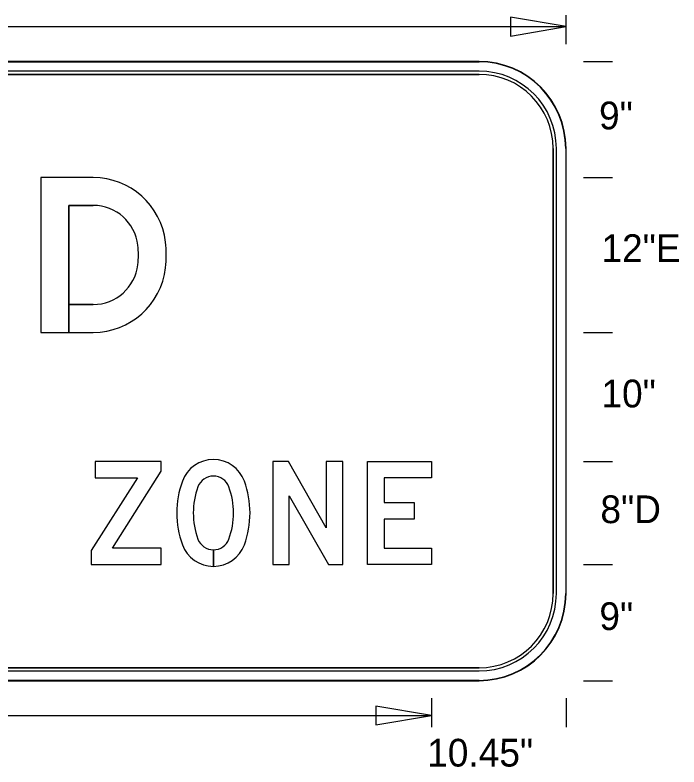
# Model space of a CAD drawing. Extents: x 0 to 770, y 0 to 495.
# Drawn here: x 679.6 to 763.5, y 379.4 to 474.2 of the extents above; entities that cross this region are included whole.
import ezdxf

# ---------------------------------------------------------------- set-up
doc = ezdxf.new("R2010")
doc.units = 0
for name, color, linetype in [('Dimension', 7, 'Continuous'), ('GSBWFill', 7, 'Continuous'), ('GSColorFill', 7, 'Continuous'), ('GSDims', 7, 'Continuous'), ('GSOutline', 7, 'Continuous'), ('TextStructures', 7, 'Continuous')]:
    doc.layers.add(name, color=color, linetype=linetype)

msp = doc.modelspace()

# ---------------------------------------------------------------- linework, layer by layer
at = {"layer": 'Dimension'}
for points in [[(749.208, 472.74), (742.192, 473.929), (742.192, 471.551)], [(732.22, 385.844), (725.203, 387.032), (725.203, 384.655)]]:
    msp.add_lwpolyline(points, close=True, dxfattribs=at)
at = {"layer": 'GSBWFill'}
for p, q in [((738.224, 468.346), (603.974, 468.346)), ((738.224, 467.126), (603.974, 467.126)), ((603.974, 466.719), (738.224, 466.719)), ((747.581, 457.362), (747.581, 401.221)), ((747.988, 401.221), (747.988, 457.362)), ((749.208, 401.221), (749.208, 457.362)), ((686.429, 434.174), (689.519, 434.174)), ((704.686, 406.738), (704.686, 404.655)), ((704.687, 404.655), (704.687, 406.738)), ((738.224, 391.864), (603.978, 391.864)), ((603.978, 391.458), (738.224, 391.458)), ((603.974, 390.237), (738.224, 390.237))]:
    msp.add_line(p, q, dxfattribs=at)
for points in [[(689.519, 453.701), (682.913, 453.701), (682.913, 434.174), (686.428, 434.174), (686.428, 450.186), (689.519, 450.186)], [(689.519, 437.688), (686.429, 437.688), (686.429, 434.174)]]:
    msp.add_lwpolyline(points, dxfattribs=at)
for points in [[(695.104, 415.818), (689.259, 406.64), (689.259, 404.883), (698.112, 404.883), (698.112, 406.966), (691.936, 406.966), (698.112, 416.664), (698.112, 417.901), (689.78, 417.901), (689.78, 415.818)], [(721.024, 404.883), (721.024, 417.901), (718.941, 417.901), (718.941, 409.537), (714.161, 417.901), (712.172, 417.901), (712.172, 404.883), (714.254, 404.883), (714.254, 413.54), (719.201, 404.883)], [(732.22, 415.818), (726.231, 415.818), (726.231, 412.694), (730.017, 412.694), (730.017, 410.611), (726.231, 410.611), (726.231, 406.966), (732.22, 406.966), (732.22, 404.883), (724.148, 404.883), (724.148, 417.901), (732.22, 417.901)]]:
    msp.add_lwpolyline(points, close=True, dxfattribs=at)
for centre, radius, start, end in [((738.224, 457.362), 10.984, 0, 90), ((738.224, 457.362), 9.764, 0, 90), ((738.224, 457.362), 9.357, 0, 90), ((689.519, 444.523), 9.178, 6.50025, 90), ((689.519, 444.523), 5.663, 6.50025, 90), ((684.378, 443.937), 10.838, 353.49975, 6.50025), ((684.378, 443.937), 14.353, 353.49975, 6.50025), ((689.519, 443.351), 5.663, 270, 353.49975), ((689.519, 443.351), 9.178, 270, 353.49975), ((704.686, 413.963), 4.166, 20.0987, 159.9013), ((704.686, 413.963), 2.083, 20.0987, 159.9013), ((711.712, 411.392), 11.648, 159.9013, 200.0987), ((711.712, 411.392), 9.565, 159.9013, 200.0987), ((697.66, 411.392), 9.565, 339.9013, 20.0987), ((697.66, 411.392), 11.648, 339.9013, 20.0987), ((704.686, 408.821), 2.083, 200.0987, 270), ((704.686, 408.821), 2.083, 270.01791, 339.9013), ((704.686, 408.821), 4.166, 200.0987, 270), ((704.686, 408.821), 4.166, 270.00895, 339.9013), ((738.224, 401.221), 9.764, 270, 0), ((738.224, 401.221), 9.357, 270, 0), ((738.224, 401.221), 10.984, 270, 0)]:
    msp.add_arc(centre, radius, start, end, dxfattribs=at)
at = {"layer": 'GSColorFill'}
for p, q in [((738.224, 468.346), (603.974, 468.346)), ((738.224, 468.346), (603.974, 468.346)), ((603.974, 468.306), (738.224, 468.306)), ((738.224, 467.126), (603.974, 467.126)), ((603.974, 466.719), (738.224, 466.719)), ((747.581, 457.362), (747.581, 401.221)), ((747.988, 401.221), (747.988, 457.362)), ((749.168, 457.362), (749.168, 401.221)), ((749.208, 401.221), (749.208, 457.362)), ((749.208, 401.221), (749.208, 457.362)), ((686.429, 434.174), (689.519, 434.174)), ((704.686, 406.738), (704.686, 404.655)), ((704.687, 404.655), (704.687, 406.738)), ((738.224, 391.864), (603.978, 391.864)), ((603.978, 391.458), (738.224, 391.458)), ((603.974, 390.237), (738.224, 390.237)), ((738.224, 390.278), (603.975, 390.278)), ((603.975, 390.237), (738.224, 390.237))]:
    msp.add_line(p, q, dxfattribs=at)
for points in [[(689.519, 453.701), (682.913, 453.701), (682.913, 434.174), (686.428, 434.174), (686.428, 450.186), (689.519, 450.186)], [(689.519, 437.688), (686.429, 437.688), (686.429, 434.174)]]:
    msp.add_lwpolyline(points, dxfattribs=at)
for points in [[(695.104, 415.818), (689.259, 406.64), (689.259, 404.883), (698.112, 404.883), (698.112, 406.966), (691.936, 406.966), (698.112, 416.664), (698.112, 417.901), (689.78, 417.901), (689.78, 415.818)], [(721.024, 404.883), (721.024, 417.901), (718.941, 417.901), (718.941, 409.537), (714.161, 417.901), (712.172, 417.901), (712.172, 404.883), (714.254, 404.883), (714.254, 413.54), (719.201, 404.883)], [(732.22, 415.818), (726.231, 415.818), (726.231, 412.694), (730.017, 412.694), (730.017, 410.611), (726.231, 410.611), (726.231, 406.966), (732.22, 406.966), (732.22, 404.883), (724.148, 404.883), (724.148, 417.901), (732.22, 417.901)]]:
    msp.add_lwpolyline(points, close=True, dxfattribs=at)
for centre, radius, start, end in [((738.224, 457.362), 10.984, 0, 90), ((738.224, 457.362), 10.984, 0, 90), ((738.224, 457.362), 10.943, 0, 90), ((738.224, 457.362), 9.764, 0, 90), ((738.224, 457.362), 9.357, 0, 90), ((689.519, 444.523), 9.178, 6.50025, 90), ((689.519, 444.523), 5.663, 6.50025, 90), ((684.378, 443.937), 10.838, 353.49975, 6.50025), ((684.378, 443.937), 14.353, 353.49975, 6.50025), ((689.519, 443.351), 5.663, 270, 353.49975), ((689.519, 443.351), 9.178, 270, 353.49975), ((704.686, 413.963), 4.166, 20.0987, 159.9013), ((704.686, 413.963), 2.083, 20.0987, 159.9013), ((711.712, 411.392), 11.648, 159.9013, 200.0987), ((711.712, 411.392), 9.565, 159.9013, 200.0987), ((697.66, 411.392), 9.565, 339.9013, 20.0987), ((697.66, 411.392), 11.648, 339.9013, 20.0987), ((704.686, 408.821), 2.083, 200.0987, 270), ((704.686, 408.821), 2.083, 270.01791, 339.9013), ((704.686, 408.821), 4.166, 200.0987, 270), ((704.686, 408.821), 4.166, 270.00895, 339.9013), ((738.224, 401.221), 10.984, 270, 0), ((738.224, 401.221), 9.764, 270, 0), ((738.224, 401.221), 9.357, 270, 0), ((738.224, 401.221), 10.984, 270, 0), ((738.224, 401.221), 10.943, 270, 0)]:
    msp.add_arc(centre, radius, start, end, dxfattribs=at)
at = {"layer": 'GSDims'}
for p, q in [((749.208, 470.543), (749.208, 474.205)), ((592.99, 472.74), (749.208, 472.74)), ((751.405, 468.346), (755.066, 468.346)), ((751.405, 453.701), (755.066, 453.701)), ((751.405, 453.701), (755.066, 453.701)), ((751.405, 434.174), (755.066, 434.174)), ((751.405, 434.174), (755.066, 434.174)), ((751.405, 417.901), (755.066, 417.901)), ((751.405, 417.901), (755.066, 417.901)), ((751.405, 404.883), (755.066, 404.883)), ((751.405, 404.883), (755.066, 404.883)), ((751.405, 390.237), (755.066, 390.237)), ((732.22, 388.04), (732.22, 384.379)), ((732.22, 388.04), (732.22, 384.379)), ((749.208, 388.04), (749.208, 384.379)), ((609.979, 385.844), (732.22, 385.844))]:
    msp.add_line(p, q, dxfattribs=at)
at = {"layer": 'GSOutline'}
for p, q in [((738.224, 468.346), (603.974, 468.346)), ((738.224, 467.126), (603.974, 467.126)), ((738.224, 466.719), (603.974, 466.719)), ((747.581, 401.221), (747.581, 457.362)), ((747.988, 401.221), (747.988, 457.362)), ((749.208, 401.221), (749.208, 457.362)), ((686.428, 437.688), (689.519, 437.688)), ((603.974, 391.864), (738.224, 391.864)), ((603.974, 391.458), (738.224, 391.458)), ((603.974, 390.237), (738.224, 390.237))]:
    msp.add_line(p, q, dxfattribs=at)
for points in [[(689.519, 453.701), (682.913, 453.701), (682.913, 434.174), (689.519, 434.174)], [(689.519, 450.186), (686.428, 450.186), (686.428, 437.688)]]:
    msp.add_lwpolyline(points, dxfattribs=at)
for points in [[(695.104, 415.818), (689.259, 406.64), (689.259, 404.883), (698.112, 404.883), (698.112, 406.966), (691.936, 406.966), (698.112, 416.664), (698.112, 417.901), (689.78, 417.901), (689.78, 415.818)], [(721.024, 404.883), (721.024, 417.901), (718.941, 417.901), (718.941, 409.537), (714.161, 417.901), (712.172, 417.901), (712.172, 404.883), (714.254, 404.883), (714.254, 413.54), (719.201, 404.883)], [(732.22, 415.818), (726.231, 415.818), (726.231, 412.694), (730.017, 412.694), (730.017, 410.611), (726.231, 410.611), (726.231, 406.966), (732.22, 406.966), (732.22, 404.883), (724.148, 404.883), (724.148, 417.901), (732.22, 417.901)]]:
    msp.add_lwpolyline(points, close=True, dxfattribs=at)
for centre, radius, start, end in [((738.224, 457.362), 10.984, 0, 90), ((738.224, 457.362), 9.764, 0, 90), ((738.224, 457.362), 9.357, 0, 90), ((689.519, 444.523), 9.178, 6.50025, 90), ((689.519, 444.523), 5.663, 6.50025, 90), ((684.378, 443.937), 10.838, 353.49975, 6.50025), ((684.378, 443.937), 14.353, 353.49975, 6.50025), ((689.519, 443.351), 5.663, 270, 353.49975), ((689.519, 443.351), 9.178, 270, 353.49975), ((704.686, 413.963), 4.166, 20.0987, 159.9013), ((704.686, 413.963), 2.083, 20.0987, 159.9013), ((711.712, 411.392), 11.648, 159.9013, 200.0987), ((711.712, 411.392), 9.565, 159.9013, 200.0987), ((697.66, 411.392), 9.565, 339.9013, 20.0987), ((697.66, 411.392), 11.648, 339.9013, 20.0987), ((704.686, 408.821), 2.083, 200.0987, 339.9013), ((704.686, 408.821), 4.166, 200.0987, 339.9013), ((738.224, 401.221), 9.764, 270, 0), ((738.224, 401.221), 9.357, 270, 0), ((738.224, 401.221), 10.984, 270, 0)]:
    msp.add_arc(centre, radius, start, end, dxfattribs=at)

# ---------------------------------------------------------------- texts
at = {"layer": 'TextStructures'}
for s, p in [('9"', (753.371, 459.784)), ('12"E', (753.676, 443.045)), ('10"', (753.676, 424.71)), ('8"D', (753.545, 410.108)), ('9"', (753.415, 396.624)), ('10.45"', (731.674, 379.401))]:
    msp.add_text(s, height=3.5, dxfattribs=at).set_placement(p)

doc.saveas('drawing.dxf')
